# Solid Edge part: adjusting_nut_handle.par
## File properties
Title: Adjusting nut handle
Author: vicky Raina
Template: Normal.par
Last saved by: CADCIM
Revision: 6
Application: Solid Edge
Density: 0 kg/mm^3
Accuracy: 0.99
Material: aluminum
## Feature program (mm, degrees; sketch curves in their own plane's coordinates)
sketch for "unnamed Protrusion 1" plane through (0, 0, 0) normal (0, -1, 0) x-axis (1, 0, 0)
  circle centre (0, 0) radius 9.5123
extrude "unnamed Protrusion 1" add finite 127 symmetric
chamfer "Chamfer_1" setback 1.5748
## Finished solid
Body 1: solid body, 5 faces, 4 edges, 0 vertices.
  Faces by surface: cone 2, plane 2, cylinder 1
  Edges by curve: circle 4
Bounding box of the edges (mm): 19.025 x 127.000 x 19.025, from (-9.5123, -63.5, -9.5123) to (9.5123, 63.5, 9.5123).
Cylindrical faces by radius (mm): R9.5123 x1
Conical faces (half-angle, radius in mm at the cone's reference point): 45 deg R7.9375 x1, 45 deg R9.5123 x1
Planar faces by outward normal: +y 1, -y 1
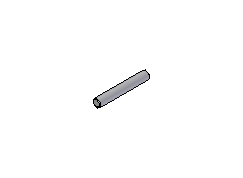
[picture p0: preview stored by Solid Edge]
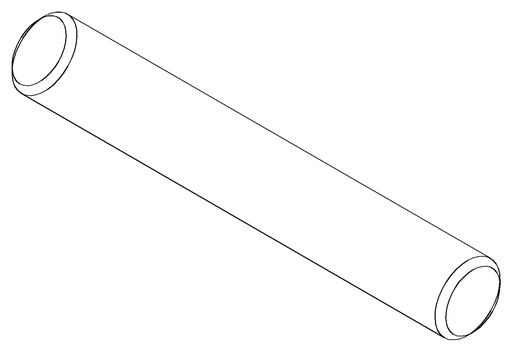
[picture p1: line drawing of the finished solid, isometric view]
